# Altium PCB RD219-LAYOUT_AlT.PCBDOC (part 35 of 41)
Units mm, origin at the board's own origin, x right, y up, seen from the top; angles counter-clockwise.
Board outline 209.75 x 159.97 mm, 2 copper layers (TOP, BOTTOM), stack 0 mm thick; 398 components, 199 nets, 1469 pads, 0 vias.
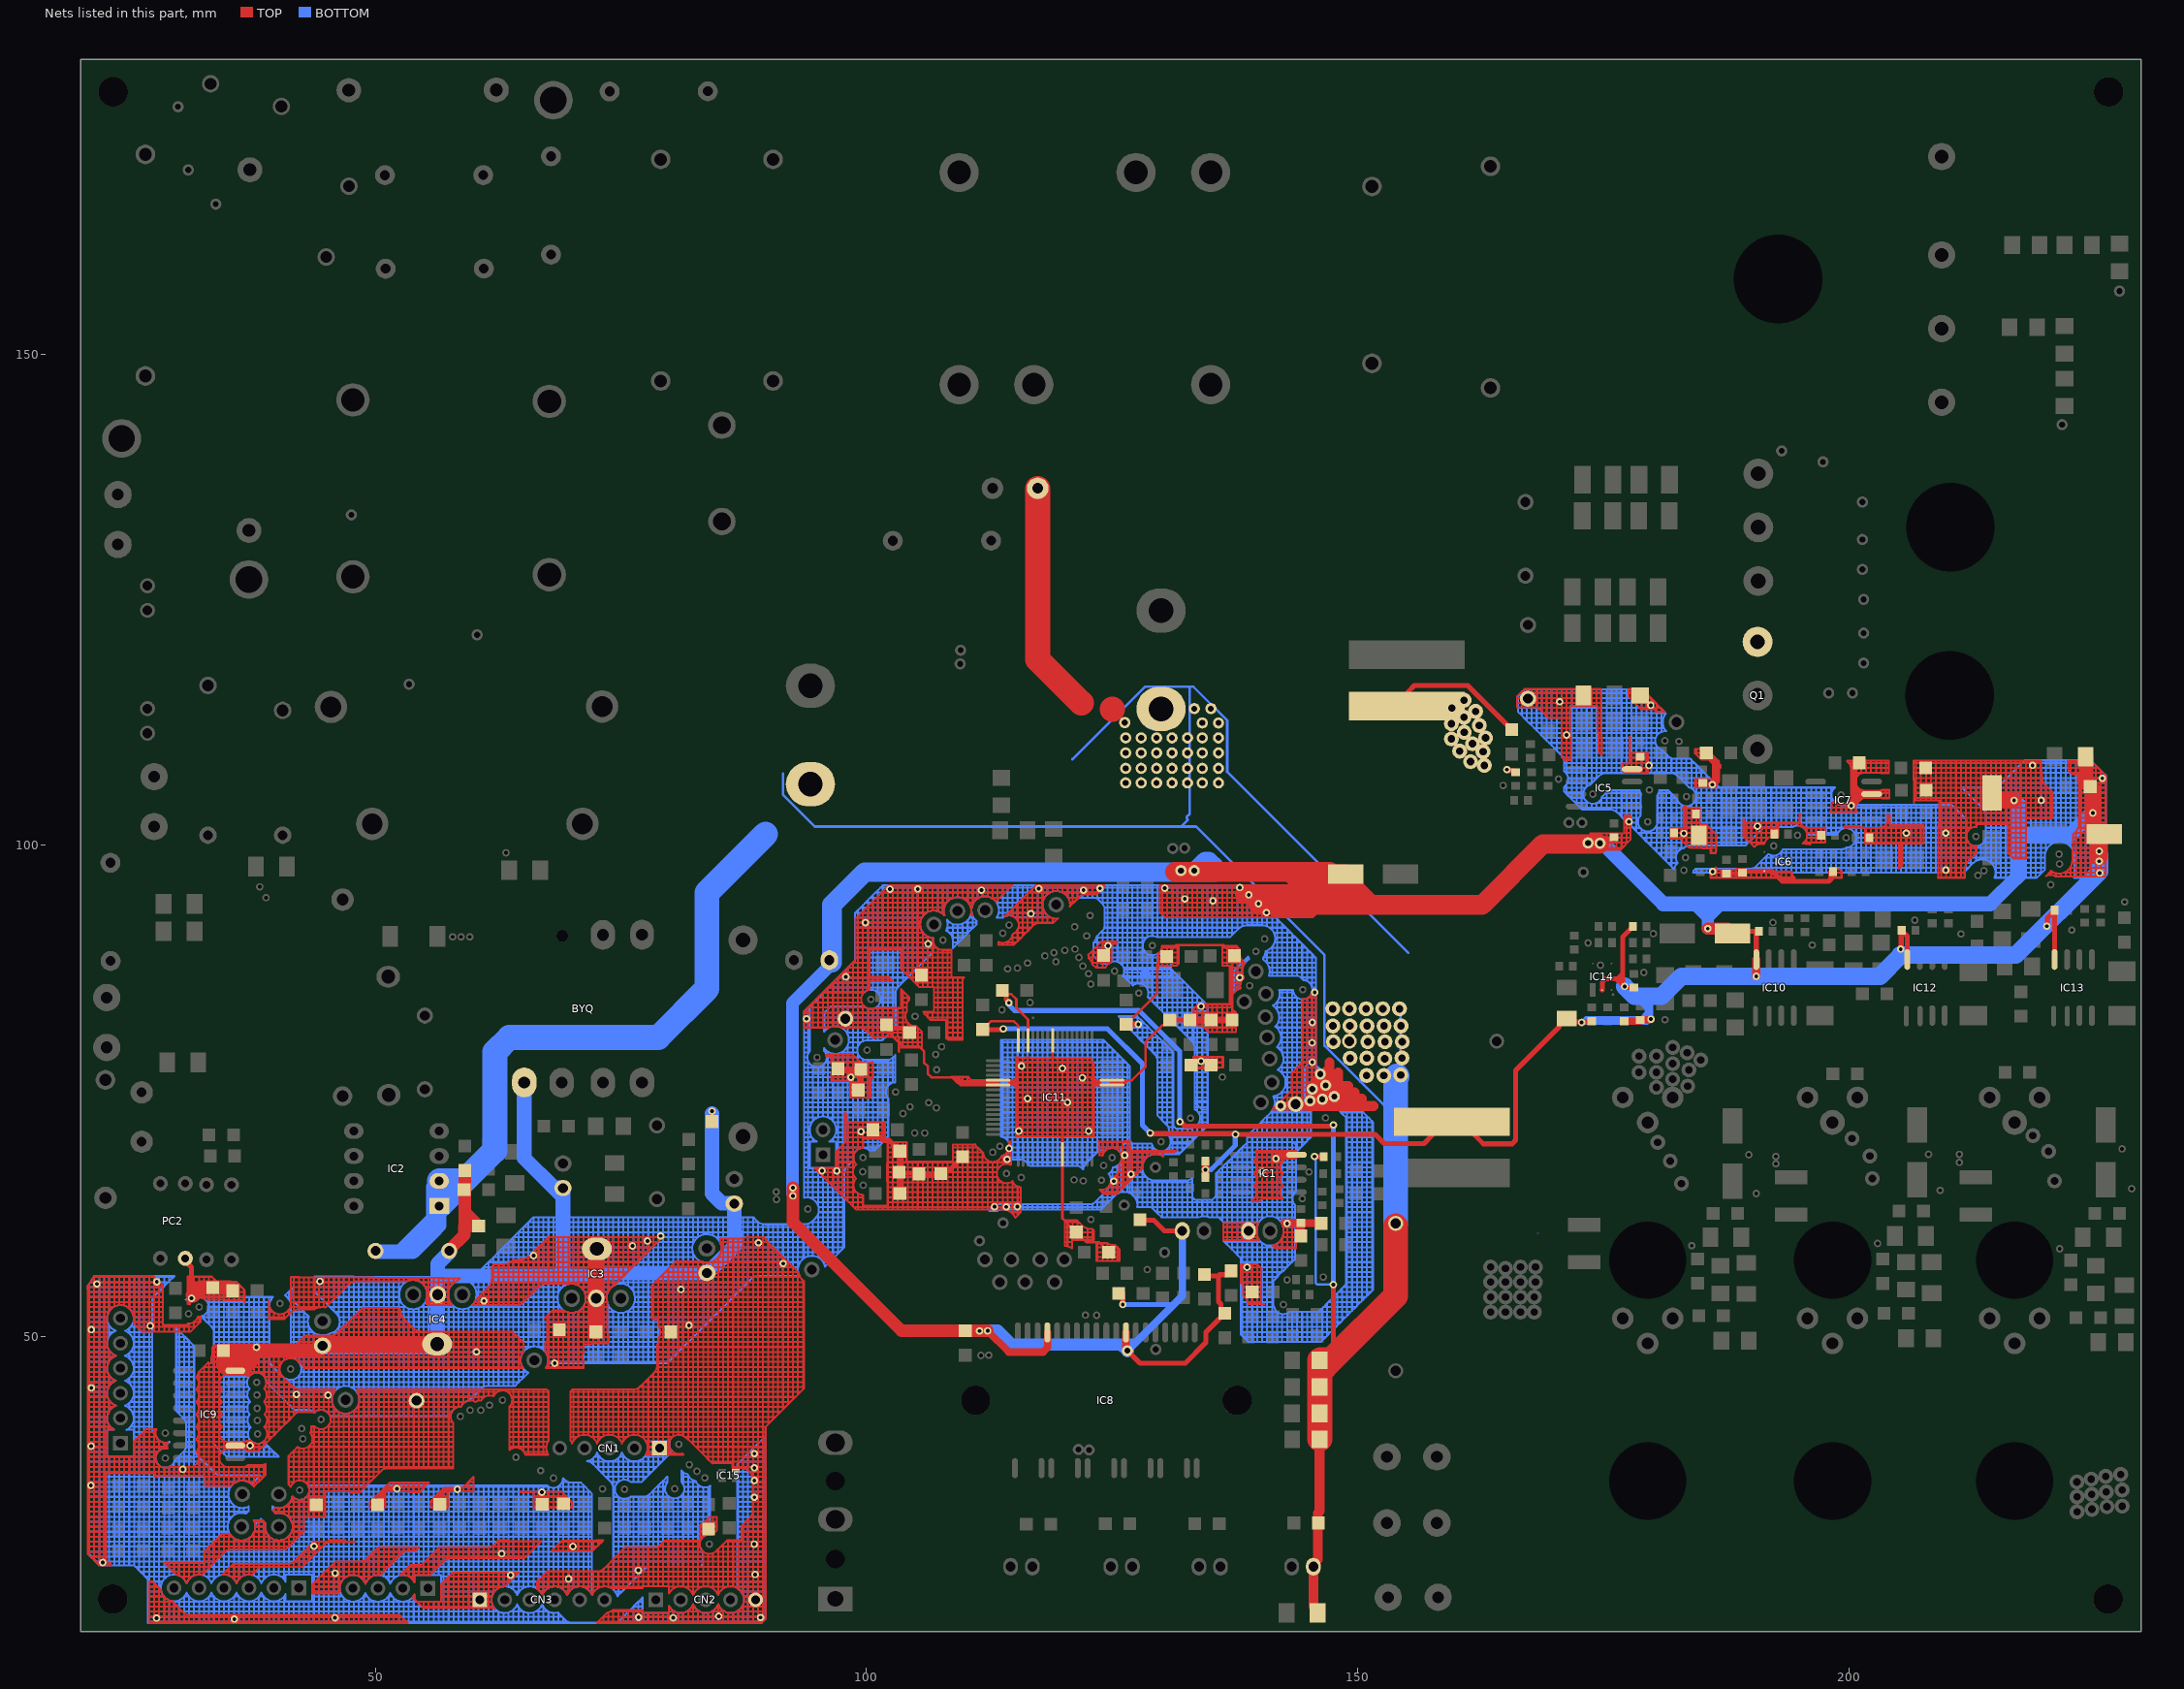
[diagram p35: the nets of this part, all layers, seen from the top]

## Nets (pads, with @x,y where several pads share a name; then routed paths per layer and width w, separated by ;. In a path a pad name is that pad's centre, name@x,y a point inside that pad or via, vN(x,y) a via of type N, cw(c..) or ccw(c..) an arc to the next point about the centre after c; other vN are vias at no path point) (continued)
GND: (continued)
  BOTTOM w0.203: pad.@144.841,74.356 pad.@145.349,74.356 ; 144.841,74.864 pad.@145.349,74.864 ; 144.841,74.864 pad.@144.841,75.372 ; pad.@144.841,75.372 pad.@145.349,75.372 ; pad.@144.841,75.372 144.841,75.88 ; 144.841,75.88 144.841,76.388 ; 144.841,75.88 145.349,75.88 ; 144.841,76.388 144.841,76.896 ; 144.841,76.388 145.349,76.388 ; 144.841,76.896 145.349,76.896 ; 144.841,76.896 144.841,77.404 ; 144.841,77.404 145.349,77.404 ; 144.841,77.404 144.841,77.658 ; 144.841,77.658 144.841,77.912 ; 144.841,77.658 pad.@145.095,77.912 ; 144.841,77.912 pad.@145.095,77.912 ; 144.841,77.912 144.841,78.42 ; 144.841,78.42 145.349,78.42 ; 144.841,78.42 144.841,78.928 ; 144.841,78.928 144.841,79.436 ; 144.841,78.928 145.349,78.928 ; 144.841,79.436 144.841,79.944 ; 144.841,79.436 145.349,79.436 ; 144.841,79.944 144.841,80.452 ; 144.841,79.944 pad.@145.349,79.944 ; 144.841,80.452 145.349,80.452 ; 144.841,80.452 144.841,80.96 ; 144.841,80.96 144.841,81.468 ; 144.841,80.96 145.349,80.96 ; 144.841,81.468 145.349,81.468 ; 144.841,81.468 144.841,81.976 ; 144.841,81.976 144.841,82.484 ; 144.841,81.976 pad.@145.349,81.976 ; 144.841,82.484 144.841,82.992 ; 144.841,82.484 145.349,82.484 ; 144.841,82.992 144.841,83.5 ; 144.841,82.992 145.349,82.992 ; 144.841,83.5 144.841,84.008 ; 144.841,83.5 145.349,83.5 ; 144.841,84.008 145.349,84.008 ; 144.841,84.008 144.841,84.444 ; 144.841,84.444 ccw(c144.396,85.32) 144.961,84.516 ; 144.841,86.548 145.349,86.548 ; 144.841,86.548 144.841,87.056 ; 144.841,87.056 144.841,87.564 ; 144.841,87.056 145.349,87.056 ; 144.841,87.564 144.841,88.072 ; 144.841,87.564 145.349,87.564 ; 144.841,88.072 145.349,88.072 ; 144.841,88.072 144.841,88.58 ; 144.841,88.58 145.349,88.58 ; 144.841,88.58 144.841,89.088 ; 144.841,89.088 144.841,89.469 ; 144.841,89.088 145.222,89.088 ; 144.841,89.469 145.222,89.088 ; 144.961,84.516 ccw(c144.396,85.32) pad.@145.333,85.024 ; 144.961,84.516 145.349,84.516 ; 144.975,73.213 145.102,73.34 ; 144.975,73.213 145.222,73.213 ; 145.064,86.04 cw(c144.396,85.32) 145.066,86.039 cw(c144.396,85.32) 145.349,85.559 ; 145.064,86.04 145.349,86.04 ; pad.@145.095,77.912 pad.@145.349,77.912 ; pad.@145.095,77.912 145.239,78.056 145.286,78.102 pad.@145.349,78.039 ; 145.102,73.34 145.164,73.402 ; 145.102,73.34 145.222,73.34 ; 145.164,73.402 145.222,73.343 145.222,73.34 ; 145.164,73.402 pad.@145.349,73.587 ; 145.222,70.292 145.222,70.8 ; 145.222,70.8 145.222,71.308 ; 145.222,71.308 145.222,71.816 ; 145.222,71.816 145.222,72.324 ; 145.222,72.324 145.222,72.832 ; 145.222,72.832 145.222,73.213 ; 145.222,73.213 145.349,73.213 ; 145.222,73.213 145.222,73.34 ; 145.222,73.34 145.349,73.34 ; 145.222,89.088 145.349,88.961 ; pad.@145.333,85.024 ccw(c144.396,85.32) pad.@145.349,85.081 ; pad.@145.333,85.024 pad.@145.349,85.024 ; 145.349,49.464 145.857,49.464 ; 145.349,49.464 145.349,49.972 ; 145.349,49.972 145.857,49.972 ; 145.349,49.972 145.349,50.48 ; 145.349,50.48 145.857,50.48 ; 145.349,50.48 145.349,50.988 ; 145.349,50.988 145.857,50.988 ; 145.349,50.988 145.349,51.496 ; 145.349,51.496 145.349,52.004 ; 145.349,51.496 145.857,51.496 ; 145.349,52.004 145.857,52.004 ; 145.349,52.004 145.349,52.512 ; 145.349,52.512 145.857,52.512 ; 145.349,73.213 145.476,73.213 145.857,73.213 ; 145.349,73.213 145.349,73.34 ; 145.349,73.34 145.857,73.34 ; 145.349,73.34 pad.@145.349,73.587 ; pad.@145.349,73.587 pad.@145.349,73.848 ; pad.@145.349,73.587 pad.@145.61,73.848 ; pad.@145.349,73.848 pad.@145.61,73.848 ; pad.@145.349,73.848 pad.@145.349,74.356 ; pad.@145.349,74.356 pad.@145.349,74.864 ; pad.@145.349,74.356 145.73,74.356 ; pad.@145.349,74.864 pad.@145.73,74.864 ; pad.@145.349,74.864 pad.@145.349,75.372 ; pad.@145.349,75.372 145.349,75.88 ; pad.@145.349,75.372 pad.@145.73,75.372 ; 145.349,75.88 145.73,75.88 ; 145.349,75.88 145.349,76.388 ; 145.349,76.388 pad.@145.73,76.388 ; 145.349,76.388 145.349,76.896 ; 145.349,76.896 pad.@145.73,76.896 ; 145.349,76.896 145.349,77.404 ; 145.349,77.404 pad.@145.349,77.912 ; 145.349,77.404 145.73,77.404 ; pad.@145.349,77.912 pad.@145.476,77.912 ; pad.@145.349,77.912 pad.@145.349,78.039 ; pad.@145.349,78.039 145.349,78.42 ; pad.@145.349,78.039 pad.@145.476,77.912 ; 145.349,78.42 145.349,78.928 ; 145.349,78.42 145.73,78.42 ; 145.349,78.928 145.349,79.436 ; 145.349,78.928 145.73,78.928 ; 145.349,79.436 145.73,79.436 ; 145.349,79.436 pad.@145.349,79.944 ; pad.@145.349,79.944 145.349,80.452 ; pad.@145.349,79.944 145.73,79.944 ; 145.349,80.452 145.73,80.452 ; 145.349,80.452 145.349,80.96 ; 145.349,80.96 145.349,81.468 ; 145.349,80.96 145.73,80.96 ; 145.349,81.468 145.73,81.468 ; 145.349,81.468 pad.@145.349,81.976 ; pad.@145.349,81.976 pad.@145.73,81.976 ; pad.@145.349,81.976 145.349,82.484 ; 145.349,82.484 145.349,82.992 ; 145.349,82.484 145.73,82.484 ; 145.349,82.992 145.349,83.5 ; 145.349,82.992 145.73,82.992 ; 145.349,83.5 145.349,84.008 ; 145.349,83.5 145.73,83.5 ; 145.349,84.008 145.349,84.516 ; 145.349,84.008 145.73,84.008 ; 145.349,84.516 pad.@145.349,85.024 ; 145.349,84.516 145.73,84.516 ; pad.@145.349,85.024 pad.@145.349,85.081 ; pad.@145.349,85.024 pad.@145.73,85.024 ; pad.@145.349,85.081 ccw(c144.396,85.32) 145.378,85.32 ccw(c144.396,85.32) 145.355,85.532 ; 145.349,85.559 cw(c144.396,85.32) 145.355,85.532 ; 145.349,85.559 145.349,86.04 ; 145.349,86.04 145.349,86.548 ; 145.349,86.04 145.73,86.04 ; 145.349,86.548 145.349,87.056 ; 145.349,86.548 145.73,86.548 ; 145.349,87.056 145.349,87.564 ; 145.349,87.056 145.73,87.056 ; 145.349,87.564 145.349,88.072 ; 145.349,87.564 145.73,87.564 ; 145.349,88.072 145.349,88.58 ; 145.349,88.072 145.73,88.072 ; 145.349,88.58 145.73,88.58 ; 145.349,88.58 145.349,88.961 ; 145.349,88.961 145.73,88.58 ; 145.355,85.532 145.73,85.532 ; pad.@145.476,77.912 145.73,77.658 ; pad.@145.476,77.912 pad.@145.73,77.912 ; pad.@145.61,73.848 145.857,73.848 ; pad.@145.61,73.848 145.73,73.968 145.73,74.356 ; 145.73,74.356 145.857,74.356 ; 145.73,74.356 pad.@145.73,74.864 ; pad.@145.73,74.864 145.857,74.864 ; pad.@145.73,74.864 pad.@145.73,75.372 ; pad.@145.73,75.372 pad.@145.857,75.372 ; pad.@145.73,75.372 145.73,75.88 ; 145.73,75.88 pad.@145.73,76.388 ; 145.73,75.88 145.857,75.88 ; pad.@145.73,76.388 pad.@145.857,76.388 ; pad.@145.73,76.388 pad.@145.73,76.896 ; pad.@145.73,76.896 145.73,77.404 ; pad.@145.73,76.896 pad.@145.857,76.896 ; 145.73,77.404 145.857,77.404 ; 145.73,77.404 145.73,77.658 ; 145.73,77.658 145.857,77.531 ; 145.73,77.658 pad.@145.73,77.912 ; pad.@145.73,77.912 145.73,78.42 ; 145.73,78.42 145.73,78.928 ; 145.73,78.928 145.73,79.436 ; 145.73,79.436 145.73,79.944 ; 145.73,79.944 145.73,80.452 ; 145.73,80.452 145.73,80.96 ; 145.73,80.96 145.73,81.468 ; 145.73,81.468 pad.@145.73,81.976 ; pad.@145.73,81.976 145.73,82.484 ; 145.73,82.484 145.73,82.992 ; 145.73,82.992 145.73,83.5 ; 145.73,83.5 145.73,84.008 ; 145.73,84.008 145.73,84.516 ; 145.73,84.516 pad.@145.73,85.024 ; pad.@145.73,85.024 145.73,85.532 ; 145.73,85.532 145.73,86.04 ; 145.73,86.04 145.73,86.548 ; 145.73,86.548 145.73,87.056 ; 145.73,87.056 145.73,87.564 ; 145.73,87.564 145.73,88.072 ; 145.73,88.072 145.73,88.58 ; 145.857,49.464 145.857,49.972 ; 145.857,49.464 146.238,49.464 146.365,49.591 ; 145.857,49.972 145.857,50.48 ; 145.857,49.972 146.365,49.972 ; 145.857,50.48 145.857,50.988 ; 145.857,50.48 146.365,50.48 ; 145.857,50.988 145.857,51.496 ; 145.857,50.988 146.365,50.988 ; 145.857,51.496 145.857,52.004 ; 145.857,51.496 146.365,51.496 ; 145.857,52.004 146.365,52.004 ; 145.857,52.004 145.857,52.512 ; 145.857,52.512 145.984,52.512 ; 145.857,73.213 145.857,73.34 ; 145.857,73.213 146.365,73.213 ; 145.857,73.34 146.365,73.34 ; 145.857,73.34 145.857,73.848 ; 145.857,73.848 pad.@146.365,73.848 ; 145.857,73.848 145.857,74.356 ; 145.857,74.356 pad.@146.365,74.356 ; 145.857,74.356 145.857,74.864 ; 145.857,74.864 146.365,74.864 ; 145.857,74.864 145.857,75.245 pad.@145.857,75.372 ; pad.@145.857,75.372 pad.@146.365,75.372 ; pad.@145.857,75.372 145.857,75.88 ; 145.857,75.88 pad.@145.857,76.388 ; 145.857,75.88 pad.@146.365,75.88 ; pad.@145.857,76.388 pad.@146.365,76.388 ; pad.@145.857,76.388 pad.@145.857,76.896 ; pad.@145.857,76.896 145.857,77.404 ; pad.@145.857,76.896 pad.@146.365,76.896 ; 145.857,77.404 145.984,77.404 ; 145.857,77.404 145.857,77.531 ; 145.857,77.531 145.984,77.404 ; 145.984,52.512 146.365,52.512 ; 145.984,52.512 146.365,52.893 ; 145.984,77.404 pad.@146.365,77.023 ; 146.365,49.591 146.746,49.972 ; 146.365,49.591 146.365,49.972 ; 146.365,49.972 146.365,50.48 ; 146.365,49.972 146.746,49.972 ; 146.365,50.48 146.365,50.988 ; 146.365,50.48 146.873,50.48 ; 146.365,50.988 146.365,51.496 ; 146.365,50.988 146.873,50.988 ; 146.365,51.496 146.365,52.004 ; 146.365,51.496 146.873,51.496 ; 146.365,52.004 146.873,52.004 ; 146.365,52.004 146.365,52.512 ; 146.365,52.512 146.873,52.512 ; 146.365,52.512 146.365,52.893 ; 146.365,52.893 146.492,53.02 ; 146.365,73.213 146.365,73.34 ; 146.365,73.34 146.873,73.34 ; 146.365,73.34 pad.@146.365,73.848 ; pad.@146.365,73.848 pad.@146.365,74.356 ; pad.@146.365,73.848 146.873,73.848 ; pad.@146.365,74.356 146.365,74.864 ; pad.@146.365,74.356 pad.@146.873,74.356 ; 146.365,74.864 146.873,74.864 ; 146.365,74.864 pad.@146.365,75.372 ; pad.@146.365,75.372 pad.@146.873,75.372 ; pad.@146.365,75.372 pad.@146.365,75.88 ; pad.@146.365,75.88 pad.@146.365,76.388 ; pad.@146.365,75.88 pad.@146.873,75.88 ; pad.@146.365,76.388 146.873,76.388 ; pad.@146.365,76.388 pad.@146.365,76.896 ; pad.@146.365,76.896 pad.@146.492,76.896 ; pad.@146.365,76.896 pad.@146.365,77.023 ; pad.@146.365,77.023 pad.@146.492,76.896 ; 146.492,53.02 146.873,53.02 ; 146.492,53.02 146.873,53.401 ; pad.@146.492,76.896 146.873,76.515 ; 146.746,49.972 146.873,50.099 ; 146.873,50.099 147.254,50.48 ; 146.873,50.099 146.873,50.48 ; 146.873,50.48 146.873,50.988 ; 146.873,50.48 147.254,50.48 ; 146.873,50.988 146.873,51.496 ; 146.873,50.988 147.381,50.988 ; 146.873,51.496 146.873,52.004 ; 146.873,51.496 147.381,51.496 ; 146.873,52.004 147.381,52.004 ; 146.873,52.004 146.873,52.512 ; 146.873,52.512 147.381,52.512 ; 146.873,52.512 146.873,53.02 ; 146.873,53.02 147.381,53.02 ; 146.873,53.02 146.873,53.401 ; 146.873,53.401 147,53.528 ; 146.873,73.243 146.873,73.34 ; 146.873,73.34 147.381,73.34 ; 146.873,73.34 146.873,73.848 ; 146.873,73.848 147.381,73.848 ; 146.873,73.848 pad.@146.873,74.356 ; pad.@146.873,74.356 pad.@147.381,74.356 ; pad.@146.873,74.356 146.873,74.864 ; 146.873,74.864 pad.@147.381,74.864 ; 146.873,74.864 pad.@146.873,75.372 ; pad.@146.873,75.372 147.381,75.372 ; pad.@146.873,75.372 pad.@146.873,75.88 ; pad.@146.873,75.88 146.873,76.388 ; pad.@146.873,75.88 147.381,75.88 ; 146.873,76.388 147,76.388 ; 146.873,76.388 146.873,76.515 ; 146.873,76.515 147,76.388 ; 147,53.528 147.381,53.528 ; 147,53.528 147.381,53.909 ; 147,76.388 147.381,76.007 ; 147.254,50.48 147.381,50.607 ; 147.381,50.607 147.762,50.988 ; 147.381,50.607 147.381,50.988 ; 147.381,50.988 147.381,51.496 ; 147.381,50.988 147.762,50.988 ; 147.381,51.496 147.381,52.004 ; 147.381,51.496 147.889,51.496 ; 147.381,52.004 147.889,52.004 ; 147.381,52.004 147.381,52.512 ; 147.381,52.512 147.889,52.512 ; 147.381,52.512 147.381,53.02 ; 147.381,53.02 147.889,53.02 ; 147.381,53.02 147.381,53.528 ; 147.381,53.528 147.889,53.528 ; 147.381,53.528 147.381,53.909 ; 147.381,53.909 147.508,54.036 ; 147.381,73.213 147.889,73.213 ; 147.381,73.213 147.381,73.34 ; 147.381,73.34 147.889,73.34 ; 147.381,73.34 147.381,73.848 ; 147.381,73.848 pad.@147.381,74.356 ; 147.381,73.848 147.889,73.848 ; pad.@147.381,74.356 pad.@147.889,74.356 ; pad.@147.381,74.356 pad.@147.381,74.864 ; pad.@147.381,74.864 147.381,75.372 ; pad.@147.381,74.864 pad.@147.889,74.864 ; 147.381,75.372 147.889,75.372 ; 147.381,75.372 147.381,75.88 ; 147.381,75.88 147.381,76.007 ; 147.381,75.88 147.508,75.88 ; 147.381,76.007 147.508,75.88 ; 147.508,54.036 147.889,54.036 ; 147.508,54.036 147.889,54.417 ; 147.508,75.88 147.889,75.499 ; 147.762,50.988 147.889,51.115 ; 147.889,51.115 148.27,51.496 ; 147.889,51.115 147.889,51.496 ; 147.889,51.496 147.889,52.004 ; 147.889,51.496 148.27,51.496 ; 147.889,52.004 147.889,52.512 ; 147.889,52.004 148.397,52.004 ; 147.889,52.512 148.397,52.512 ; 147.889,52.512 147.889,53.02 ; 147.889,53.02 148.397,53.02 ; 147.889,53.02 147.889,53.528 ; 147.889,53.528 148.397,53.528 ; 147.889,53.528 147.889,54.036 ; 147.889,54.036 148.397,54.036 ; 147.889,54.036 147.889,54.417 ; 147.889,54.417 148.016,54.544 ; 147.889,73.213 147.889,73.34 ; 147.889,73.213 148.27,72.832 ; 147.889,73.34 148.397,73.34 ; 147.889,73.34 147.889,73.848 ; 147.889,73.848 148.397,73.848 ; 147.889,73.848 pad.@147.889,74.356 ; pad.@147.889,74.356 148.397,74.356 ; pad.@147.889,74.356 pad.@147.889,74.864 ; pad.@147.889,74.864 148.397,74.864 ; pad.@147.889,74.864 147.889,75.372 ; 147.889,75.372 148.016,75.372 ; 147.889,75.372 147.889,75.499 ; 147.889,75.499 148.016,75.372 ; 148.016,54.544 148.397,54.925 ; 148.016,54.544 148.397,54.544 ; 148.016,75.372 148.397,74.991 ; 148.27,51.496 148.397,51.623 ; 148.27,72.832 148.397,72.832 ; 148.27,72.832 148.397,72.705 ; 148.397,51.623 148.778,52.004 ; 148.397,51.623 148.397,52.004 ; 148.397,52.004 148.397,52.512 ; 148.397,52.004 148.778,52.004 ; 148.397,52.512 148.905,52.512 ; 148.397,52.512 148.397,53.02 ; 148.397,53.02 148.905,53.02 ; 148.397,53.02 148.397,53.528 ; 148.397,53.528 148.905,53.528 ; 148.397,53.528 148.397,54.036 ; 148.397,54.036 148.905,54.036 ; 148.397,54.036 148.397,54.544 ; 148.397,54.544 148.905,54.544 ; 148.397,54.544 148.397,54.925 ; 148.397,54.925 148.524,55.052 ; 148.397,72.705 148.397,72.832 ; 148.397,72.705 148.778,72.324 ; 148.397,72.832 148.397,73.34 ; 148.397,72.832 148.905,72.832 ; 148.397,73.34 148.905,73.34 ; 148.397,73.34 148.397,73.848 ; 148.397,73.848 148.905,73.848 ; 148.397,73.848 148.397,74.356 ; 148.397,74.356 148.905,74.356 ; 148.397,74.356 148.397,74.864 ; 148.397,74.864 148.524,74.864 ; 148.397,74.864 148.397,74.991 ; 148.397,74.991 148.524,74.864 ; 148.524,55.052 148.778,55.306 148.778,55.56 ; 148.524,55.052 148.905,55.052 ; 148.524,74.864 148.905,74.483 ; 148.778,52.004 148.905,52.131 ; 148.778,55.56 148.905,55.56 ; 148.778,55.56 148.778,56.068 ; 148.778,56.068 148.905,56.068 ; 148.778,56.068 148.778,56.576 ; 148.778,56.576 148.905,56.576 ; 148.778,56.576 148.778,57.084 ; 148.778,57.084 148.905,57.084 ; 148.778,57.084 148.778,57.592 ; 148.778,57.592 148.905,57.592 ; 148.778,57.592 148.778,58.1 ; 148.778,58.1 148.905,58.1 ; 148.778,58.1 148.778,58.608 ; 148.778,58.608 148.905,58.608 ; 148.778,58.608 148.778,59.116 ; 148.778,59.116 148.905,59.116 ; 148.778,59.116 148.778,59.624 ; 148.778,59.624 148.905,59.624 ; 148.778,59.624 148.778,60.132 ; 148.778,60.132 148.905,60.132 ; 148.778,60.132 148.778,60.64 ; 148.778,60.64 148.905,60.64 ; 148.778,60.64 148.778,61.148 ; 148.778,61.148 148.905,61.148 ; 148.778,61.148 148.778,61.656 ; 148.778,61.656 148.905,61.656 ; 148.778,61.656 148.778,62.164 ; 148.778,62.164 148.905,62.164 ; 148.778,62.164 148.778,62.672 ; 148.778,62.672 148.905,62.672 ; 148.778,62.672 148.778,63.18 ; 148.778,63.18 148.905,63.18 ; 148.778,63.18 148.778,63.688 ; 148.778,63.688 148.905,63.688 ; 148.778,63.688 148.778,64.196 ; 148.778,64.196 148.905,64.196 ; 148.778,64.196 148.778,64.704 ; 148.778,64.704 148.905,64.704 ; 148.778,64.704 148.778,65.212 ; 148.778,65.212 148.905,65.212 ; 148.778,65.212 148.778,65.72 ; 148.778,65.72 148.905,65.72 ; 148.778,65.72 148.778,66.228 ; 148.778,66.228 148.905,66.228 ; 148.778,66.228 148.778,66.736 ; 148.778,66.736 148.905,66.736 ; 148.778,66.736 148.778,67.244 ; 148.778,67.244 148.905,67.244 ; 148.778,67.244 148.778,67.752 ; 148.778,67.752 148.905,67.752 ; 148.778,67.752 148.778,68.26 ; 148.778,68.26 148.905,68.26 ; 148.778,68.26 148.778,68.768 ; 148.778,68.768 148.905,68.768 ; 148.778,68.768 148.778,69.276 ; 148.778,69.276 148.905,69.276 ; 148.778,69.276 148.778,69.784 ; 148.778,69.784 148.905,69.784 ; 148.778,69.784 148.778,70.292 ; 148.778,70.292 148.905,70.292 ; 148.778,70.292 148.778,70.8 ; 148.778,70.8 148.905,70.8 ; 148.778,70.8 148.778,71.308 ; 148.778,71.308 148.778,71.816 ; 148.778,71.308 148.905,71.308 ; 148.778,71.816 148.905,71.816 ; 148.778,71.816 148.778,72.324 ; 148.778,72.324 148.905,72.324 ; 148.905,52.131 148.905,52.512 ; 148.905,52.131 149.286,52.512 ; 148.905,52.512 148.905,53.02 ; 148.905,52.512 149.286,52.512 ; 148.905,53.02 149.413,53.02 ; 148.905,53.02 148.905,53.528 ; 148.905,53.528 149.413,53.528 ; 148.905,53.528 148.905,54.036 ; 148.905,54.036 149.413,54.036 ; 148.905,54.036 148.905,54.544 ; 148.905,54.544 149.413,54.544 ; 148.905,54.544 148.905,55.052 ; 148.905,55.052 148.905,55.56 ; 148.905,55.052 149.413,55.052 ; 148.905,55.56 148.905,56.068 ; 148.905,55.56 149.413,55.56 ; 148.905,56.068 148.905,56.576 ; 148.905,56.068 149.413,56.068 ; 148.905,56.576 148.905,57.084 ; 148.905,56.576 149.413,56.576 ; 148.905,57.084 148.905,57.592 ; 148.905,57.084 149.413,57.084 ; 148.905,57.592 148.905,58.1 ; 148.905,57.592 149.413,57.592 ; 148.905,58.1 148.905,58.608 ; 148.905,58.1 149.413,58.1 ; 148.905,58.608 148.905,59.116 ; 148.905,58.608 149.413,58.608 ; 148.905,59.116 148.905,59.624 ; 148.905,59.116 149.413,59.116 ; 148.905,59.624 148.905,60.132 ; 148.905,59.624 149.413,59.624 ; 148.905,60.132 148.905,60.64 ; 148.905,60.132 149.413,60.132 ; 148.905,60.64 148.905,61.148 ; 148.905,60.64 149.413,60.64 ; 148.905,61.148 148.905,61.656 ; 148.905,61.148 149.413,61.148 ; 148.905,61.656 148.905,62.164 ; 148.905,61.656 149.413,61.656 ; 148.905,62.164 148.905,62.672 ; 148.905,62.164 149.413,62.164 ; 148.905,62.672 148.905,63.18 ; 148.905,62.672 149.413,62.672 ; 148.905,63.18 148.905,63.688 ; 148.905,63.18 149.413,63.18 ; 148.905,63.688 148.905,64.196 ; 148.905,63.688 149.413,63.688 ; 148.905,64.196 148.905,64.704 ; 148.905,64.196 149.413,64.196 ; 148.905,64.704 148.905,65.212 ; 148.905,64.704 149.413,64.704 ; 148.905,65.212 148.905,65.72 ; 148.905,65.212 149.413,65.212 ; 148.905,65.72 148.905,66.228 ; 148.905,65.72 149.413,65.72 ; 148.905,66.228 148.905,66.736 ; 148.905,66.228 149.413,66.228 ; 148.905,66.736 148.905,67.244 ; 148.905,66.736 149.413,66.736 ; 148.905,67.244 148.905,67.752 ; 148.905,67.244 149.413,67.244 ; 148.905,67.752 148.905,68.26 ; 148.905,67.752 149.413,67.752 ; 148.905,68.26 148.905,68.768 ; 148.905,68.26 149.413,68.26 ; 148.905,68.768 148.905,69.276 ; 148.905,68.768 149.413,68.768 ; 148.905,69.276 148.905,69.784 ; 148.905,69.276 149.413,69.276 ; 148.905,69.784 148.905,70.292 ; 148.905,69.784 149.413,69.784 ; 148.905,70.292 148.905,70.8 ; 148.905,70.292 149.413,70.292 ; 148.905,70.8 148.905,71.308 ; 148.905,70.8 149.413,70.8 ; 148.905,71.308 148.905,71.816 ; 148.905,71.308 149.413,71.308 ; 148.905,71.816 149.413,71.816 ; 148.905,71.816 148.905,72.324 ; 148.905,72.324 149.413,72.324 ; 148.905,72.324 148.905,72.832 ; 148.905,72.832 149.413,72.832 ; 148.905,72.832 148.905,73.34 ; 148.905,73.34 149.413,73.34 ; 148.905,73.34 148.905,73.848 ; 148.905,73.848 149.413,73.848 ; 148.905,73.848 148.905,74.356 ; 148.905,74.356 149.032,74.356 ; 148.905,74.356 148.905,74.483 ; 148.905,74.483 149.032,74.356 ; 149.032,74.356 149.413,73.975 ; 149.286,52.512 149.413,52.639 ; 149.413,52.639 149.413,53.02 ; 149.413,52.639 149.794,53.02 ; 149.413,53.02 149.413,53.528 ; 149.413,53.02 149.794,53.02 ; 149.413,53.528 149.921,53.528 ; 149.413,53.528 149.413,54.036 ; 149.413,54.036 149.921,54.036 ; 149.413,54.036 149.413,54.544 ; 149.413,54.544 149.921,54.544 ; 149.413,54.544 149.413,55.052 ; 149.413,55.052 149.413,55.56 ; 149.413,55.052 149.921,55.052 ; 149.413,55.56 149.413,56.068 ; 149.413,55.56 149.921,55.56 ; 149.413,56.068 149.413,56.576 ; 149.413,56.068 149.921,56.068 ; 149.413,56.576 149.413,57.084 ; 149.413,56.576 149.921,56.576 ; 149.413,57.084 149.413,57.592 ; 149.413,57.084 149.921,57.084 ; 149.413,57.592 149.413,58.1 ; 149.413,57.592 149.921,57.592 ; 149.413,58.1 149.413,58.608 ; 149.413,58.1 149.921,58.1 ; 149.413,58.608 149.413,59.116 ; 149.413,58.608 149.921,58.608 ; 149.413,59.116 149.413,59.624 ; 149.413,59.116 149.921,59.116 ; 149.413,59.624 149.413,60.132 ; 149.413,59.624 149.921,59.624 ; 149.413,60.132 149.413,60.64 ; 149.413,60.132 149.921,60.132 ; 149.413,60.64 149.413,61.148 ; 149.413,60.64 149.921,60.64 ; 149.413,61.148 149.413,61.656 ; 149.413,61.148 149.921,61.148 ; 149.413,61.656 149.413,62.164 ; 149.413,61.656 149.921,61.656 ; 149.413,62.164 149.413,62.672 ; 149.413,62.164 149.921,62.164 ; 149.413,62.672 149.413,63.18 ; 149.413,62.672 149.921,62.672 ; 149.413,63.18 149.413,63.688 ; 149.413,63.18 149.921,63.18 ; 149.413,63.688 149.413,64.196 ; 149.413,63.688 149.921,63.688 ; 149.413,64.196 149.413,64.704 ; 149.413,64.196 149.921,64.196 ; 149.413,64.704 149.413,65.212 ; 149.413,64.704 149.921,64.704 ; 149.413,65.212 149.413,65.72 ; 149.413,65.212 149.921,65.212 ; 149.413,65.72 149.413,66.228 ; 149.413,65.72 149.921,65.72 ; 149.413,66.228 149.413,66.736 ; 149.413,66.228 149.921,66.228 ; 149.413,66.736 149.413,67.244 ; 149.413,66.736 149.921,66.736 ; 149.413,67.244 149.413,67.752 ; 149.413,67.244 149.921,67.244 ; 149.413,67.752 149.413,68.26 ; 149.413,67.752 149.921,67.752 ; 149.413,68.26 149.413,68.768 ; 149.413,68.26 149.921,68.26 ; 149.413,68.768 149.413,69.276 ; 149.413,68.768 149.921,68.768 ; 149.413,69.276 149.413,69.784 ; 149.413,69.276 149.921,69.276 ; 149.413,69.784 149.413,70.292 ; 149.413,69.784 149.921,69.784 ; 149.413,70.292 149.413,70.8 ; 149.413,70.292 149.921,70.292 ; 149.413,70.8 149.413,71.308 ; 149.413,70.8 149.921,70.8 ; 149.413,71.308 149.413,71.816 ; 149.413,71.308 149.921,71.308 ; 149.413,71.816 149.921,71.816 ; 149.413,71.816 149.413,72.324 ; 149.413,72.324 149.921,72.324 ; 149.413,72.324 149.413,72.832 ; 149.413,72.832 149.921,72.832 ; 149.413,72.832 149.413,73.34 ; 149.413,73.34 149.921,73.34 ; 149.413,73.34 149.413,73.848 ; 149.413,73.848 149.54,73.848 ; 149.413,73.848 149.413,73.975 ; 149.413,73.975 149.54,73.848 ; 149.54,73.848 149.921,73.467 ; 149.794,53.02 149.921,53.147 ; 149.921,53.147 149.921,53.528 ; 149.921,53.147 150.302,53.528 ; 149.921,53.528 150.302,53.528 ; 149.921,53.528 149.921,54.036 ; 149.921,54.036 150.429,54.036 ; 149.921,54.036 149.921,54.544 ; 149.921,54.544 150.429,54.544 ; 149.921,54.544 149.921,55.052 ; 149.921,55.052 149.921,55.56 ; 149.921,55.052 150.429,55.052 ; 149.921,55.56 149.921,56.068 ; 149.921,55.56 150.429,55.56 ; 149.921,56.068 149.921,56.576 ; 149.921,56.068 150.429,56.068 ; 149.921,56.576 149.921,57.084 ; 149.921,56.576 150.429,56.576 ; 149.921,57.084 149.921,57.592 ; 149.921,57.084 150.429,57.084 ; 149.921,57.592 149.921,58.1 ; 149.921,57.592 150.429,57.592 ; 149.921,58.1 149.921,58.608 ; 149.921,58.1 150.429,58.1 ; 149.921,58.608 149.921,59.116 ; 149.921,58.608 150.429,58.608 ; 149.921,59.116 149.921,59.624 ; 149.921,59.116 150.429,59.116 ; 149.921,59.624 149.921,60.132 ; 149.921,59.624 150.429,59.624 ; 149.921,60.132 149.921,60.64 ; 149.921,60.132 150.429,60.132 ; 149.921,60.64 149.921,61.148 ; 149.921,60.64 150.429,60.64 ; 149.921,61.148 149.921,61.656 ; 149.921,61.148 150.429,61.148 ; 149.921,61.656 149.921,62.164 ; 149.921,61.656 150.429,61.656 ; 149.921,62.164 149.921,62.672 ; 149.921,62.164 150.429,62.164 ; 149.921,62.672 149.921,63.18 ; 149.921,62.672 150.429,62.672 ; 149.921,63.18 149.921,63.688 ; 149.921,63.18 150.429,63.18 ; 149.921,63.688 149.921,64.196 ; 149.921,63.688 150.429,63.688 ; 149.921,64.196 149.921,64.704 ; 149.921,64.196 150.429,64.196 ; 149.921,64.704 149.921,65.212 ; 149.921,64.704 150.429,64.704 ; 149.921,65.212 149.921,65.72 ; 149.921,65.212 150.429,65.212 ; 149.921,65.72 149.921,66.228 ; 149.921,65.72 150.429,65.72 ; 149.921,66.228 149.921,66.736 ; 149.921,66.228 150.429,66.228 ; 149.921,66.736 149.921,67.244 ; 149.921,66.736 150.429,66.736 ; 149.921,67.244 149.921,67.752 ; 149.921,67.244 150.429,67.244 ; 149.921,67.752 149.921,68.26 ; 149.921,67.752 150.429,67.752 ; 149.921,68.26 149.921,68.768 ; 149.921,68.26 150.429,68.26 ; 149.921,68.768 149.921,69.276 ; 149.921,68.768 150.429,68.768 ; 149.921,69.276 149.921,69.784 ; 149.921,69.276 150.429,69.276 ; 149.921,69.784 149.921,70.292 ; 149.921,69.784 150.429,69.784 ; 149.921,70.292 149.921,70.8 ; 149.921,70.292 150.429,70.292 ; 149.921,70.8 149.921,71.308 ; 149.921,70.8 150.429,70.8 ; 149.921,71.308 149.921,71.816 ; 149.921,71.308 150.429,71.308 ; 149.921,71.816 150.429,71.816 ; 149.921,71.816 149.921,72.324 ; 149.921,72.324 150.429,72.324 ; 149.921,72.324 149.921,72.832 ; 149.921,72.832 150.429,72.832 ; 149.921,72.832 149.921,73.34 ; 149.921,73.34 150.048,73.34 ; 149.921,73.34 149.921,73.467 ; 149.921,73.467 150.048,73.34 ; 150.048,73.34 150.429,72.959 ; 150.302,53.528 150.429,53.655 ; 150.429,53.655 150.429,54.036 ; 150.429,53.655 150.81,54.036 ; 150.429,54.036 150.429,54.544 ; 150.429,54.036 150.81,54.036 ; 150.429,54.544 150.429,55.052 ; 150.429,54.544 150.937,54.544 ; 150.429,55.052 150.429,55.56 ; 150.429,55.052 150.937,55.052 ; 150.429,55.56 150.429,56.068 ; 150.429,55.56 150.937,55.56 ; 150.429,56.068 150.429,56.576 ; 150.429,56.068 150.937,56.068 ; 150.429,56.576 150.429,57.084 ; 150.429,56.576 150.937,56.576 ; 150.429,57.084 150.429,57.592 ; 150.429,57.084 150.937,57.084 ; 150.429,57.592 150.429,58.1 ; 150.429,57.592 150.937,57.592 ; 150.429,58.1 150.429,58.608 ; 150.429,58.1 150.937,58.1 ; 150.429,58.608 150.429,59.116 ; 150.429,58.608 150.937,58.608 ; 150.429,59.116 150.429,59.624 ; 150.429,59.116 150.937,59.116 ; 150.429,59.624 150.429,60.132 ; 150.429,59.624 150.937,59.624 ; 150.429,60.132 150.429,60.64 ; 150.429,60.132 150.937,60.132 ; 150.429,60.64 150.429,61.148 ; 150.429,60.64 150.937,60.64 ; 150.429,61.148 150.429,61.656 ; 150.429,61.148 150.937,61.148 ; 150.429,61.656 150.429,62.164 ; 150.429,61.656 150.937,61.656 ; 150.429,62.164 150.429,62.672 ; 150.429,62.164 150.937,62.164 ; 150.429,62.672 150.429,63.18 ; 150.429,62.672 150.937,62.672 ; 150.429,63.18 150.429,63.688 ; 150.429,63.18 150.937,63.18 ; 150.429,63.688 150.429,64.196 ; 150.429,63.688 150.937,63.688 ; 150.429,64.196 150.429,64.704 ; 150.429,64.196 150.937,64.196 ; 150.429,64.704 150.429,65.212 ; 150.429,64.704 150.937,64.704 ; 150.429,65.212 150.429,65.72 ; 150.429,65.212 150.937,65.212 ; 150.429,65.72 150.429,66.228 ; 150.429,65.72 150.937,65.72 ; 150.429,66.228 150.429,66.736 ; 150.429,66.228 150.937,66.228 ; 150.429,66.736 150.429,67.244 ; 150.429,66.736 150.937,66.736 ; 150.429,67.244 150.429,67.752 ; 150.429,67.244 150.937,67.244 ; 150.429,67.752 150.429,68.26 ; 150.429,67.752 150.937,67.752 ; 150.429,68.26 150.429,68.768 ; 150.429,68.26 150.937,68.26 ; 150.429,68.768 150.429,69.276 ; 150.429,68.768 150.937,68.768 ; 150.429,69.276 150.429,69.784 ; 150.429,69.276 150.937,69.276 ; 150.429,69.784 150.429,70.292 ; 150.429,69.784 150.937,69.784 ; 150.429,70.292 150.429,70.8 ; 150.429,70.292 150.937,70.292 ; 150.429,70.8 150.429,71.308 ; 150.429,70.8 150.937,70.8 ; 150.429,71.308 150.429,71.816 ; 150.429,71.308 150.937,71.308 ; 150.429,71.816 150.937,71.816 ; 150.429,71.816 150.429,72.324 ; 150.429,72.324 150.937,72.324 ; 150.429,72.324 150.429,72.832 ; 150.429,72.832 150.556,72.832 ; 150.429,72.832 150.429,72.959 ; 150.429,72.959 150.556,72.832 ; 150.556,72.832 150.937,72.451 ; 150.81,54.036 150.937,54.163 ; 150.937,54.163 150.937,54.544 ; 150.937,54.163 151.318,54.544 ; 150.937,54.544 150.937,55.052 ; 150.937,54.544 151.318,54.544 ; 150.937,55.052 150.937,55.56 ; 150.937,55.052 151.445,55.052 ; 150.937,55.56 150.937,56.068 ; 150.937,55.56 151.445,55.56 ; 150.937,56.068 150.937,56.576 ; 150.937,56.068 151.445,56.068 ; 150.937,56.576 150.937,57.084 ; 150.937,56.576 151.445,56.576 ; 150.937,57.084 150.937,57.592 ; 150.937,57.084 151.445,57.084 ; 150.937,57.592 150.937,58.1 ; 150.937,57.592 151.445,57.592 ; 150.937,58.1 150.937,58.608 ; 150.937,58.1 151.445,58.1 ; 150.937,58.608 150.937,59.116 ; 150.937,58.608 151.445,58.608 ; 150.937,59.116 150.937,59.624 ; 150.937,59.116 151.445,59.116 ; 150.937,59.624 150.937,60.132 ; 150.937,59.624 151.445,59.624 ; 150.937,60.132 150.937,60.64 ; 150.937,60.132 151.445,60.132 ; 150.937,60.64 150.937,61.148 ; 150.937,60.64 151.445,60.64 ; 150.937,61.148 150.937,61.656 ; 150.937,61.148 151.445,61.148 ; 150.937,61.656 150.937,62.164 ; 150.937,61.656 151.445,61.656 ; 150.937,62.164 150.937,62.672 ; 150.937,62.164 151.445,62.164 ; 150.937,62.672 150.937,63.18 ; 150.937,62.672 151.445,62.672 ; 150.937,63.18 150.937,63.688 ; 150.937,63.18 151.445,63.18 ; 150.937,63.688 150.937,64.196 ; 150.937,63.688 151.445,63.688 ; 150.937,64.196 150.937,64.704 ; 150.937,64.196 151.445,64.196 ; 150.937,64.704 150.937,65.212 ; 150.937,64.704 151.445,64.704 ; 150.937,65.212 150.937,65.72 ; 150.937,65.212 151.445,65.212 ; 150.937,65.72 150.937,66.228 ; 150.937,65.72 151.445,65.72 ; 150.937,66.228 150.937,66.736 ; 150.937,66.228 151.445,66.228 ; 150.937,66.736 150.937,67.244 ; 150.937,66.736 151.445,66.736 ; 150.937,67.244 150.937,67.752 ; 150.937,67.244 151.445,67.244 ; 150.937,67.752 150.937,68.26 ; 150.937,67.752 151.445,67.752 ; 150.937,68.26 150.937,68.768 ; 150.937,68.26 151.445,68.26 ; 150.937,68.768 150.937,69.276 ; 150.937,68.768 151.445,68.768 ; 150.937,69.276 150.937,69.784 ; 150.937,69.276 151.445,69.276 ; 150.937,69.784 150.937,70.292 ; 150.937,69.784 151.445,69.784 ; 150.937,70.292 150.937,70.8 ; 150.937,70.292 151.445,70.292 ; 150.937,70.8 150.937,71.308 ; 150.937,70.8 151.445,70.8 ; 150.937,71.308 150.937,71.816 ; 150.937,71.308 151.445,71.308 ; 150.937,71.816 151.445,71.816 ; 150.937,71.816 150.937,72.324 ; 150.937,72.324 151.064,72.324 ; 150.937,72.324 150.937,72.451 ; 150.937,72.451 151.064,72.324 ; 151.064,72.324 151.445,71.943 ; 151.318,54.544 151.445,54.671 ; 151.445,54.671 151.572,54.798 151.572,55.052 ; 151.445,54.671 151.445,55.052 ; 151.445,55.052 151.445,55.56 ; 151.445,55.052 151.572,55.052 ; 151.445,55.56 151.445,56.068 ; 151.445,55.56 151.572,55.56 ; 151.445,56.068 151.445,56.576 ; 151.445,56.068 151.572,56.068 ; 151.445,56.576 151.445,57.084 ; 151.445,56.576 151.572,56.576 ; 151.445,57.084 151.572,57.084 ; 151.445,57.084 151.445,57.592 ; 151.445,57.592 151.572,57.592 ; 151.445,57.592 151.445,58.1 ; 151.445,58.1 151.572,58.1 ; 151.445,58.1 151.445,58.608 ; 151.445,58.608 151.572,58.608 ; 151.445,58.608 151.445,59.116 ; 151.445,59.116 151.572,59.116 ; 151.445,59.116 151.445,59.624 ; 151.445,59.624 151.572,59.624 ; 151.445,59.624 151.445,60.132 ; 151.445,60.132 151.572,60.132 ; 151.445,60.132 151.445,60.64 ; 151.445,60.64 151.572,60.64 ; 151.445,60.64 151.445,61.148 ; 151.445,61.148 151.572,61.148 ; 151.445,61.148 151.445,61.656 ; 151.445,61.656 151.572,61.656 ; 151.445,61.656 151.445,62.164 ; 151.445,62.164 151.572,62.164 ; 151.445,62.164 151.445,62.672 ; 151.445,62.672 151.572,62.672 ; 151.445,62.672 151.445,63.18 ; 151.445,63.18 151.572,63.18 ; 151.445,63.18 151.445,63.688 ; 151.445,63.688 151.572,63.688 ; 151.445,63.688 151.445,64.196 ; 151.445,64.196 151.572,64.196 ; 151.445,64.196 151.445,64.704 ; 151.445,64.704 151.572,64.704 ; 151.445,64.704 151.445,65.212 ; 151.445,65.212 151.572,65.212 ; 151.445,65.212 151.445,65.72 ; 151.445,65.72 151.572,65.72 ; 151.445,65.72 151.445,66.228 ; 151.445,66.228 151.572,66.228 ; 151.445,66.228 151.445,66.736 ; 151.445,66.736 151.572,66.736 ; 151.445,66.736 151.445,67.244 ; 151.445,67.244 151.572,67.244 ; 151.445,67.244 151.445,67.752 ; 151.445,67.752 151.572,67.752 ; 151.445,67.752 151.445,68.26 ; 151.445,68.26 151.572,68.26 ; 151.445,68.26 151.445,68.768 ; 151.445,68.768 151.572,68.768 ; 151.445,68.768 151.445,69.276 ; 151.445,69.276 151.572,69.276 ; 151.445,69.276 151.445,69.784 ; 151.445,69.784 151.572,69.784 ; 151.445,69.784 151.445,70.292 ; 151.445,70.292 151.572,70.292 ; 151.445,70.292 151.445,70.8 ; 151.445,70.8 151.572,70.8 ; 151.445,70.8 151.445,71.308 ; 151.445,71.308 151.445,71.816 ; 151.445,71.308 151.572,71.308 ; 151.445,71.816 151.572,71.816 ; 151.445,71.816 151.445,71.943 ; 151.445,71.943 151.572,71.816 ; 151.572,55.052 151.572,55.56 ; 151.572,55.56 151.572,56.068 ; 151.572,56.068 151.572,56.576 ; 151.572,56.576 151.572,57.084 ; 151.572,57.084 151.572,57.592 ; 151.572,57.592 151.572,58.1 ; 151.572,58.1 151.572,58.608 ; 151.572,58.608 151.572,59.116 ; 151.572,59.116 151.572,59.624 ; 151.572,59.624 151.572,60.132 ; 151.572,60.132 151.572,60.64 ; 151.572,60.64 151.572,61.148 ; 151.572,61.148 151.572,61.656 ; 151.572,61.656 151.572,62.164 ; 151.572,62.164 151.572,62.672 ; 151.572,62.672 151.572,63.18 ; 151.572,63.18 151.572,63.688 ; 151.572,63.688 151.572,64.196 ; 151.572,64.196 151.572,64.704 ; 151.572,64.704 151.572,65.212 ; 151.572,65.212 151.572,65.72 ; 151.572,65.72 151.572,66.228 ; 151.572,66.228 151.572,66.736 ; 151.572,66.736 151.572,67.244 ; 151.572,67.244 151.572,67.752 ; 151.572,67.752 151.572,68.26 ; 151.572,68.26 151.572,68.768 ; 151.572,68.768 151.572,69.276 ; 151.572,69.276 151.572,69.784 ; 151.572,69.784 151.572,70.292 ; 151.572,70.292 151.572,70.8 ; 151.572,70.8 151.572,71.308 ; 151.572,71.308 151.572,71.816 ; 166.304,113.98 166.685,113.98 ; 166.304,113.98 166.304,114.488 ; 166.304,113.98 166.304,113.599 166.431,113.472 ; 166.304,114.488 166.685,114.488 ; 166.304,114.488 166.304,114.996 ; 166.304,114.996 166.685,114.996 ; 166.304,114.996 166.304,115.123 166.685,115.504 ; 166.431,113.472 166.685,113.472 ; 166.431,113.472 166.685,113.218 ; 166.685,113.218 166.939,112.964 ; 166.685,113.218 166.685,113.472 ; 166.685,113.472 167.193,113.472 ; 166.685,113.472 166.685,113.98 ; 166.685,113.98 167.193,113.98 ; 166.685,113.98 166.685,114.488 ; 166.685,114.488 167.193,114.488 ; 166.685,114.488 166.685,114.996 ; 166.685,114.996 167.193,114.996 ; 166.685,114.996 166.685,115.504 ; 166.685,115.504 167.193,115.504 ; 166.685,115.504 167.066,115.885 167.193,115.885 ; 166.939,112.964 167.193,112.964 ; 166.939,112.964 167.193,112.71 ; 167.193,112.71 167.447,112.456 ; 167.193,112.71 167.193,112.964 ; 167.193,112.964 167.701,112.964 ; 167.193,112.964 167.193,113.472 ; 167.193,113.472 167.701,113.472 ; 167.193,113.472 167.193,113.98 ; 167.193,113.98 167.701,113.98 ; 167.193,113.98 167.193,114.488 ; 167.193,114.488 167.193,114.996 ; 167.193,114.488 167.701,114.488 ; 167.193,114.996 167.193,115.504 ; 167.193,114.996 167.701,114.996 ; 167.193,115.504 167.193,115.885 ; 167.193,115.504 167.701,115.504 ; 167.193,115.885 167.701,115.885 ; 167.447,112.456 167.701,112.456 ; 167.447,112.456 167.701,112.202 ; 167.701,112.202 167.955,111.948 ; 167.701,112.202 167.701,112.456 ; 167.701,112.456 168.209,112.456 ; 167.701,112.456 167.701,112.964 ; 167.701,112.964 168.209,112.964 ; 167.701,112.964 167.701,113.472 ; 167.701,113.472 168.209,113.472 ; 167.701,113.472 167.701,113.98 ; 167.701,113.98 168.209,113.98 ; 167.701,113.98 167.701,114.488 ; 167.701,114.488 168.209,114.488 ; 167.701,114.488 167.701,114.996 ; 167.701,114.996 168.209,114.996 ; 167.701,114.996 167.701,115.504 ; 167.701,115.504 168.209,115.504 ; 167.701,115.504 167.701,115.885 ; 167.701,115.885 168.209,115.885 ; 167.955,111.948 168.209,111.948 ; 167.955,111.948 168.209,111.694 ; 168.209,111.694 168.463,111.44 ; 168.209,111.694 168.209,111.948 ; 168.209,111.948 168.717,111.948 ; 168.209,111.948 168.209,112.456 ; 168.209,112.456 168.717,112.456 ; 168.209,112.456 168.209,112.964 ; 168.209,112.964 168.717,112.964 ; 168.209,112.964 168.209,113.472 ; 168.209,113.472 168.717,113.472 ; 168.209,113.472 168.209,113.98 ; 168.209,113.98 168.717,113.98 ; 168.209,113.98 168.209,114.488 ; 168.209,114.488 168.717,114.488 ; 168.209,114.488 168.209,114.996 ; 168.209,114.996 168.717,114.996 ; 168.209,114.996 168.209,115.504 ; 168.209,115.504 168.717,115.504 ; 168.209,115.504 168.209,115.885 ; 168.209,115.885 168.717,115.885 ; 168.463,111.44 168.717,111.44 ; 168.463,111.44 168.717,111.186 ; 168.717,111.186 168.717,111.44 ; 168.717,111.186 168.971,110.932 ; 168.717,111.44 169.225,111.44 ; 168.717,111.44 168.717,111.948 ; 168.717,111.948 169.225,111.948 ; 168.717,111.948 168.717,112.456 ; 168.717,112.456 169.225,112.456 ; 168.717,112.456 168.717,112.964 ; 168.717,112.964 169.225,112.964 ; 168.717,112.964 168.717,113.472 ; 168.717,113.472 169.225,113.472 ; 168.717,113.472 168.717,113.98 ; 168.717,113.98 169.225,113.98 ; 168.717,113.98 168.717,114.488 ; 168.717,114.488 169.225,114.488 ; 168.717,114.488 168.717,114.996 ; 168.717,114.996 169.225,114.996 ; 168.717,114.996 168.717,115.504 ; 168.717,115.504 169.225,115.504 ; 168.717,115.504 168.717,115.885 ; 168.717,115.885 169.225,115.885 ; 168.971,110.932 169.225,110.932 ; 168.971,110.932 169.225,110.678 ; 169.225,110.678 169.225,110.932 ; 169.225,110.678 169.479,110.424 ; 169.225,110.932 169.733,110.932 ; 169.225,110.932 169.225,111.44 ; 169.225,111.44 169.733,111.44 ; 169.225,111.44 169.225,111.948 ; 169.225,111.948 169.733,111.948 ; 169.225,111.948 169.225,112.456 ; 169.225,112.456 169.733,112.456 ; 169.225,112.456 169.225,112.964 ; 169.225,112.964 169.733,112.964 ; 169.225,112.964 169.225,113.472 ; 169.225,113.472 169.733,113.472 ; 169.225,113.472 169.225,113.98 ; 169.225,113.98 169.733,113.98 ; 169.225,113.98 169.225,114.488 ; 169.225,114.488 169.733,114.488 ; 169.225,114.488 169.225,114.996 ; 169.225,114.996 169.733,114.996 ; 169.225,114.996 169.225,115.504 ; 169.225,115.504 169.733,115.504 ; 169.225,115.504 169.225,115.885 ; 169.225,115.885 169.733,115.885 ; 169.479,110.424 169.733,110.424 ; 169.479,110.424 169.733,110.17 ; 169.733,110.17 169.733,110.424 ; 169.733,110.17 169.987,109.916 ; 169.733,110.424 170.241,110.424 ; 169.733,110.424 169.733,110.932 ; 169.733,110.932 170.241,110.932 ; 169.733,110.932 169.733,111.44 ; 169.733,111.44 170.241,111.44 ; 169.733,111.44 169.733,111.948 ; 169.733,111.948 170.241,111.948 ; 169.733,111.948 169.733,112.456 ; 169.733,112.456 170.241,112.456 ; 169.733,112.456 169.733,112.964 ; 169.733,112.964 170.241,112.964 ; 169.733,112.964 169.733,113.472 ; 169.733,113.472 170.241,113.472 ; 169.733,113.472 169.733,113.98 ; 169.733,113.98 170.241,113.98 ; 169.733,113.98 169.733,114.488 ; 169.733,114.488 pad.@170.241,114.488 ; 169.733,114.488 169.733,114.996 ; 169.733,114.996 170.241,114.996 ; 169.733,114.996 169.733,115.504 ; 169.733,115.504 170.241,115.504 ; 169.733,115.504 169.733,115.885 ; 169.733,115.885 170.241,115.885 ; 169.987,109.916 170.241,109.916 ; 169.987,109.916 170.241,109.662 ; 170.241,109.662 170.241,109.916 ; 170.241,109.662 170.495,109.408 ; 170.241,109.916 170.749,109.916 ; 170.241,109.916 170.241,110.424 ; 170.241,110.424 170.749,110.424 ; 170.241,110.424 170.241,110.932 ; 170.241,110.932 170.749,110.932 ; 170.241,110.932 170.241,111.44 ; 170.241,111.44 170.749,111.44 ; 170.241,111.44 170.241,111.948 ; 170.241,111.948 170.749,111.948 ; 170.241,111.948 170.241,112.456 ; 170.241,112.456 170.749,112.456 ; 170.241,112.456 170.241,112.964 ; 170.241,112.964 170.749,112.964 ; 170.241,112.964 170.241,113.472 ; 170.241,113.472 170.749,113.472 ; 170.241,113.472 170.241,113.98 ; 170.241,113.98 170.749,113.98 ; 170.241,113.98 pad.@170.241,114.488 ; pad.@170.241,114.488 170.241,114.996 ; pad.@170.241,114.488 pad.@170.749,114.488 ; 170.241,114.996 170.241,115.504 ; 170.241,114.996 170.749,114.996 ; 170.241,115.504 170.749,115.504 ; 170.241,115.504 170.241,115.885 ; 170.241,115.885 170.749,115.885 ; 170.495,109.408 170.749,109.408 ; 170.495,109.408 170.749,109.154 ; 170.749,109.154 170.749,109.408 ; 170.749,109.154 171.003,108.9 ; 170.749,109.408 171.257,109.408 ; 170.749,109.408 170.749,109.916 ; 170.749,109.916 171.257,109.916 ; 170.749,109.916 170.749,110.424 ; 170.749,110.424 171.257,110.424 ; 170.749,110.424 170.749,110.932 ; 170.749,110.932 170.749,111.44 ; 170.749,110.932 pad.@171.257,110.932 ; 170.749,111.44 170.749,111.948 ; 170.749,111.44 pad.@171.257,111.44 ; 170.749,111.948 171.257,111.948 ; 170.749,111.948 170.749,112.456 ; 170.749,112.456 171.257,112.456 ; 170.749,112.456 170.749,112.964 ; 170.749,112.964 171.257,112.964 ; 170.749,112.964 170.749,113.472 ; 170.749,113.472 171.257,113.472 ; 170.749,113.472 170.749,113.98 ; 170.749,113.98 171.257,113.98 ; 170.749,113.98 pad.@170.749,114.488 ; pad.@170.749,114.488 171.257,114.488 ; pad.@170.749,114.488 170.749,114.996 ; 170.749,114.996 171.257,114.996 ; 170.749,114.996 170.749,115.504 ; 170.749,115.504 171.257,115.504 ; 170.749,115.504 170.749,115.885 ; 170.749,115.885 171.257,115.885 ; 171.003,105.852 171.257,105.852 ; 171.003,105.852 171.003,105.471 171.13,105.344 ; 171.003,108.392 171.257,108.392 ; 171.003,108.392 171.003,108.9 ; 171.003,108.9 171.257,108.9 ; 171.13,105.344 171.257,105.344 ; 171.13,105.344 171.257,105.217 ; 171.18,107.376 cw(c170.428,106.744) 171.257,107.271 ; 171.18,107.376 171.257,107.376 ; 171.257,105.217 171.638,104.836 ; 171.257,105.217 171.257,105.344 ; 171.257,105.344 171.765,105.344 ; 171.257,105.344 171.257,105.852 ; 171.257,105.852 171.765,105.852 ; 171.257,105.852 171.257,106.216 ; 171.257,106.216 ccw(c170.428,106.744) 171.332,106.36 ; 171.257,107.271 cw(c170.428,106.744) 171.403,106.868 ; 171.257,107.271 171.257,107.376 ; 171.257,107.376 171.765,107.376 ; 171.257,107.376 171.257,107.884 ; 171.257,107.884 171.765,107.884 ; 171.257,107.884 171.257,108.392 ; 171.257,108.392 171.765,108.392 ; 171.257,108.392 171.257,108.9 ; 171.257,108.9 171.765,108.9 ; 171.257,108.9 171.257,109.408 ; 171.257,109.408 171.765,109.408 ; 171.257,109.408 171.257,109.916 ; 171.257,109.916 171.765,109.916 ; 171.257,109.916 171.257,110.424 ; 171.257,110.424 171.765,110.424 ; 171.257,110.424 pad.@171.257,110.932 ; pad.@171.257,110.932 171.765,110.932 ; pad.@171.257,110.932 pad.@171.257,111.44 ; pad.@171.257,111.44 171.765,111.44 ; pad.@171.257,111.44 171.257,111.948 ; 171.257,111.948 171.765,111.948 ; 171.257,111.948 171.257,112.456 ; 171.257,112.456 171.765,112.456 ; 171.257,112.456 171.257,112.964 ; 171.257,112.964 171.765,112.964 ; 171.257,112.964 171.257,113.472 ; 171.257,113.472 171.765,113.472 ; 171.257,113.472 171.257,113.98 ; 171.257,113.98 171.765,113.98 ; 171.257,113.98 171.257,114.488 ; 171.257,114.488 171.765,114.488 ; 171.257,114.488 171.257,114.996 ; 171.257,114.996 171.765,114.996 ; 171.257,114.996 171.257,115.504 ; 171.257,115.504 171.765,115.504 ; 171.257,115.504 171.257,115.885 ; 171.257,115.885 171.765,115.885 ; 171.332,106.36 ccw(c170.428,106.744) 171.403,106.868 ; 171.332,106.36 171.765,106.36 ; 171.403,106.868 171.765,106.868 ; 171.638,104.836 171.765,104.836 ; 171.638,104.836 171.765,104.709 ; 171.765,104.709 171.765,104.836 ; 171.765,104.709 172.146,104.328 ; 171.765,104.836 171.765,105.344 ; 171.765,104.836 172.273,104.836 ; 171.765,105.344 171.765,105.852 ; 171.765,105.344 172.273,105.344 ; 171.765,105.852 171.765,106.36 ; 171.765,105.852 172.273,105.852 ; 171.765,106.36 172.273,106.36 ; 171.765,106.36 171.765,106.868 ; 171.765,106.868 172.273,106.868 ; 171.765,106.868 171.765,107.376 ; 171.765,107.376 172.273,107.376 ; 171.765,107.376 171.765,107.884 ; 171.765,107.884 172.273,107.884 ; 171.765,107.884 171.765,108.392 ; 171.765,108.392 172.273,108.392 ; 171.765,108.392 171.765,108.9 ; 171.765,108.9 172.273,108.9 ; 171.765,108.9 171.765,109.408 ; 171.765,109.408 172.273,109.408 ; 171.765,109.408 171.765,109.916 ; 171.765,109.916 172.273,109.916 ; 171.765,109.916 171.765,110.424 ; 171.765,110.424 172.273,110.424 ; 171.765,110.424 171.765,110.932 ; 171.765,110.932 172.273,110.932 ; 171.765,110.932 171.765,111.44 ; 171.765,111.44 172.273,111.44 ; 171.765,111.44 171.765,111.948 ; 171.765,111.948 172.273,111.948 ; 171.765,111.948 171.765,112.456 ; 171.765,112.456 172.273,112.456 ; 171.765,112.456 171.765,112.964 ; 171.765,112.964 172.273,112.964 ; 171.765,112.964 171.765,113.472 ; 171.765,113.472 172.273,113.472 ; 171.765,113.472 171.765,113.98 ; 171.765,113.98 172.273,113.98 ; 171.765,113.98 171.765,114.488 ; 171.765,114.488 172.273,114.488 ; 171.765,114.488 171.765,114.996 ; 171.765,114.996 172.273,114.996 ; 171.765,114.996 171.765,115.504 ; 171.765,115.504 172.273,115.504 ; 171.765,115.504 171.765,115.885 ; 171.765,115.885 172.273,115.885 ; 172.146,104.328 172.273,104.328 ; 172.146,104.328 172.273,104.201 ; 172.273,104.201 172.273,104.328 ; 172.273,104.201 172.654,103.82 ; 172.273,104.328 172.273,104.836 ; 172.273,104.328 172.781,104.328 ; 172.273,104.836 172.273,105.344 ; 172.273,104.836 172.781,104.836 ; 172.273,105.344 172.273,105.852 ; 172.273,105.344 172.781,105.344 ; 172.273,105.852 172.273,106.36 ; 172.273,105.852 172.781,105.852 ; 172.273,106.36 172.781,106.36 ; 172.273,106.36 172.273,106.868 ; 172.273,106.868 172.781,106.868 ; 172.273,106.868 172.273,107.376 ; 172.273,107.376 172.781,107.376 ; 172.273,107.376 172.273,107.884 ; 172.273,107.884 172.781,107.884 ; 172.273,107.884 172.273,108.392 ; 172.273,108.392 172.781,108.392 ; 172.273,108.392 172.273,108.9 ; 172.273,108.9 172.781,108.9 ; 172.273,108.9 172.273,109.408 ; 172.273,109.408 172.781,109.408 ; 172.273,109.408 172.273,109.916 ; 172.273,109.916 172.781,109.916 ; 172.273,109.916 172.273,110.424 ; 172.273,110.424 172.781,110.424 ; 172.273,110.424 172.273,110.932 ; 172.273,110.932 172.781,110.932 ; 172.273,110.932 172.273,111.44 ; 172.273,111.44 172.781,111.44 ; 172.273,111.44 172.273,111.948 ; 172.273,111.948 172.781,111.948 ; 172.273,111.948 172.273,112.456 ; 172.273,112.456 172.781,112.456 ; 172.273,112.456 172.273,112.964 ; 172.273,112.964 172.781,112.964 ; 172.273,112.964 172.273,113.472 ; 172.273,113.472 172.781,113.472 ; 172.273,113.472 172.273,113.98 ; 172.273,113.98 172.781,113.98 ; 172.273,113.98 172.273,114.488 ; 172.273,114.488 172.781,114.488 ; 172.273,114.488 172.273,114.996 ; 172.273,114.996 172.781,114.996 ; 172.273,114.996 172.273,115.504 ; 172.273,115.504 172.781,115.504 ; 172.273,115.504 172.273,115.885 ; 172.273,115.885 172.781,115.885 ; 172.654,103.82 172.781,103.82 ; 172.654,103.82 172.781,103.693 ; 172.781,103.693 172.781,103.82 ; 172.781,103.82 172.781,104.328 ; 172.781,103.82 173.289,103.82 ; 172.781,104.328 172.781,104.836 ; 172.781,104.328 173.289,104.328 ; 172.781,104.836 172.781,105.344 ; 172.781,104.836 173.018,104.836 ; 172.781,105.344 172.781,105.852 ; 172.781,105.344 172.95,105.344 ; 172.781,105.852 172.781,106.36 ; 172.781,105.852 173.174,105.852 ; 172.781,106.36 173.289,106.36 ; 172.781,106.36 172.781,106.868 ; 172.781,106.868 173.289,106.868 ; 172.781,106.868 172.781,107.376 ; 172.781,107.376 173.289,107.376 ; 172.781,107.376 172.781,107.884 ; 172.781,107.884 173.289,107.884 ; 172.781,107.884 172.781,108.392 ; 172.781,108.392 173.289,108.392 ; 172.781,108.392 172.781,108.9 ; 172.781,108.9 173.289,108.9 ; 172.781,108.9 172.781,109.408 ; 172.781,109.408 173.289,109.408 ; 172.781,109.408 172.781,109.916 ; 172.781,109.916 173.289,109.916 ; 172.781,109.916 172.781,110.424 ; 172.781,110.424 173.289,110.424 ; 172.781,110.424 172.781,110.932 ; 172.781,110.932 173.289,110.932 ; 172.781,110.932 172.781,111.44 ; 172.781,111.44 173.289,111.44 ; 172.781,111.44 172.781,111.948 ; 172.781,111.948 173.289,111.948 ; 172.781,111.948 172.781,112.456 ; 172.781,112.456 173.289,112.456 ; 172.781,112.456 172.781,112.964 ; 172.781,112.964 173.289,112.964 ; 172.781,112.964 172.781,113.472 ; 172.781,113.472 173.289,113.472 ; 172.781,113.472 172.781,113.98 ; 172.781,113.98 173.289,113.98 ; 172.781,113.98 172.781,114.488 ; 172.781,114.488 173.289,114.488 ; 172.781,114.488 172.781,114.996 ; 172.781,114.996 173.289,114.996 ; 172.781,114.996 172.781,115.504 ; 172.781,115.504 173.289,115.504 ; 172.781,115.504 172.781,115.885 ; 172.781,115.885 173.289,115.885 ; 172.95,105.344 ccw(c173.924,105.217) 173.018,104.836 ; 172.95,105.344 cw(c173.924,105.217) 173.174,105.852 ; 173.018,104.836 ccw(c173.924,105.217) 173.289,104.467 ; 173.174,105.852 cw(c173.924,105.217) 173.289,105.967 ; 173.289,103.667 173.289,103.82 ; 173.289,103.667 173.797,103.667 ; 173.289,103.82 173.289,104.328 ; 173.289,103.82 173.797,103.82 ; 173.289,104.328 173.289,104.467 ; 173.289,104.328 173.505,104.328 ; 173.289,104.467 ccw(c173.924,105.217) 173.292,104.464 ccw(c173.924,105.217) 173.505,104.328 ; 173.289,105.967 173.289,106.36 ; 173.289,106.36 173.289,106.868 ; 173.289,106.36 173.797,106.36 ; 173.289,106.868 173.289,107.376 ; 173.289,106.868 173.797,106.868 ; 173.289,107.376 173.289,107.884 ; 173.289,107.376 173.797,107.376 ; 173.289,107.884 173.289,108.392 ; 173.289,107.884 173.797,107.884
